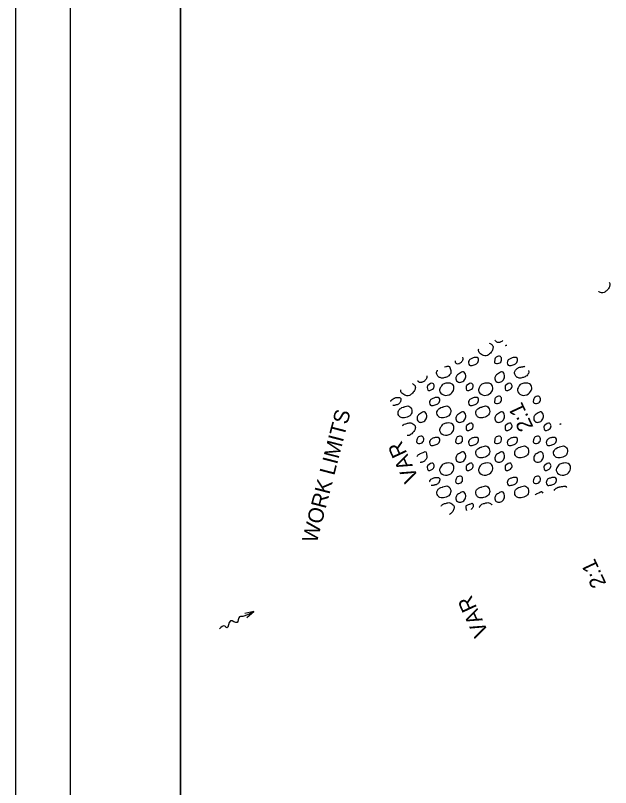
# Model space of a CAD drawing. Extents: x 0 to 2278, y -264 to 330.
# Drawn here: x 0 to 81.2, y 163.9 to 269.1 of the extents above; entities that cross this region are included whole.
import ezdxf

# ---------------------------------------------------------------- set-up
doc = ezdxf.new("R2010")
doc.units = 0
for name, color, linetype in [('DR_P_Culvert', 7, 'Continuous'), ('RW_X_CL_100_Stations', 7, 'Continuous'), ('SC_Scratch1', 7, 'Continuous'), ('XS_P_Finished_Grade', 7, 'Continuous'), ('XS_P_Pavt_Surface', 7, 'Continuous')]:
    doc.layers.add(name, color=color, linetype=linetype)

msp = doc.modelspace()

# ---------------------------------------------------------------- linework, layer by layer
at = {"layer": 'RW_X_CL_100_Stations'}
for points in [[(7.5, 322.5), (22.5, 322.5), (22.5, 7.5), (7.5, 7.5)], [(22.5, 322.5), (502.5, 322.5), (502.5, 7.5), (22.5, 7.5)]]:
    msp.add_lwpolyline(points, close=True, dxfattribs=at)
at = {"layer": 'SC_Scratch1'}
msp.add_lwpolyline([(0, 0), (510, 0), (510, 330), (0, 330)], close=True, dxfattribs=at)
at = {"layer": 'XS_P_Finished_Grade'}
for points, degree in [([(80.96, 232.75), (81.08, 232.59), (81.08, 232.39), (81.03, 232.24), (80.96, 232), (80.82, 231.78), (80.59, 231.58), (80.3, 231.34), (79.91, 231.25), (79.62, 231.42), (79.59, 231.44), (79.56, 231.45), (79.53, 231.47)], 3), ([(64.61, 224.44), (64.72, 224.4), (64.83, 224.34), (64.93, 224.25), (65.13, 224.08), (65.15, 223.83), (65.09, 223.65), (65.03, 223.41), (64.88, 223.19), (64.65, 222.99), (64.37, 222.75), (63.97, 222.65), (63.68, 222.83), (63.44, 222.97), (63.19, 223.18), (63.15, 223.42), (63.13, 223.51), (63.15, 223.6), (63.18, 223.68)], 3), ([(66.48, 224.81), (66.34, 224.67), (66.19, 224.6), (66.03, 224.55), (65.89, 224.51), (65.71, 224.5), (65.57, 224.64), (65.5, 224.71), (65.45, 224.78), (65.41, 224.86)], 3), ([(66.82, 224.12), (66.88, 224.14), (66.94, 224.17), (67, 224.19)], 2), ([(60.96, 222.52), (61.01, 222.41), (61.01, 222.23), (60.98, 222.14), (60.92, 221.98), (60.77, 221.81), (60.62, 221.7), (60.46, 221.58), (60.13, 221.6), (60.04, 221.78), (60, 221.86), (60, 221.94), (60.01, 222.02)], 3), ([(58.49, 221.23), (58.65, 221.25), (58.81, 221.28), (58.96, 221.3), (59.19, 221.33), (59.3, 220.95), (59.35, 220.73), (59.4, 220.54), (59.37, 220.3), (59.21, 220.12), (59.01, 219.9), (58.79, 219.82), (58.54, 219.74), (58.33, 219.68), (58.09, 219.66), (57.88, 219.75), (57.75, 219.8), (57.66, 219.9), (57.58, 220.02), (57.45, 220.22), (57.41, 220.49), (57.53, 220.68), (57.54, 220.7), (57.55, 220.72), (57.56, 220.74)], 3), ([(69.97, 220.7), (70.01, 220.51), (69.97, 220.29), (69.82, 220.12), (69.62, 219.9), (69.39, 219.82), (69.15, 219.74), (68.93, 219.68), (68.7, 219.66), (68.49, 219.75), (68.36, 219.8), (68.27, 219.9), (68.19, 220.02), (68.06, 220.22), (68.02, 220.49), (68.13, 220.68), (68.21, 220.81), (68.31, 220.92), (68.44, 221), (68.55, 221.07), (68.66, 221.14), (68.78, 221.17), (68.82, 221.17), (68.86, 221.18), (68.9, 221.19)], 3), ([(68.89, 221.19), (69.08, 221.22), (69.28, 221.26), (69.47, 221.29)], 2), ([(56.1, 219.97), (56.12, 219.79), (56.07, 219.6), (55.92, 219.43), (55.77, 219.25), (55.6, 219.16), (55.42, 219.11), (55.28, 219.06), (55.1, 219.06), (54.96, 219.2), (54.92, 219.24), (54.88, 219.28), (54.86, 219.32)], 3), ([(54.13, 218.94), (54.19, 218.9), (54.26, 218.86), (54.33, 218.8), (54.53, 218.64), (54.54, 218.39), (54.49, 218.2), (54.42, 217.97), (54.27, 217.74), (54.04, 217.55), (53.76, 217.3), (53.36, 217.21), (53.07, 217.38), (52.83, 217.52), (52.58, 217.73), (52.54, 217.98), (52.53, 218.02), (52.53, 218.06), (52.54, 218.1)], 3), ([(51.18, 216.49), (51.19, 216.54), (51.21, 216.59), (51.24, 216.63), (51.27, 216.68), (51.31, 216.73), (51.35, 216.78)], 3), ([(51.35, 216.78), (51.47, 216.84), (51.6, 216.9), (51.72, 216.96), (51.86, 217.03), (52.03, 217.05), (52.18, 217.05), (52.29, 217.05), (52.39, 217.03), (52.49, 216.93), (52.58, 216.84), (52.57, 216.72), (52.54, 216.62), (52.5, 216.47), (52.44, 216.31), (52.29, 216.18), (52.14, 216.06), (51.98, 216.04), (51.82, 216), (51.7, 215.97), (51.57, 215.92), (51.45, 215.93)], 3), ([(53.01, 213.42), (53.19, 213.46), (53.37, 213.51), (53.54, 213.56), (53.8, 213.62), (54.07, 213.58), (54.33, 213.36), (54.53, 213.19), (54.54, 212.94), (54.49, 212.75), (54.42, 212.52), (54.27, 212.3), (54.04, 212.1), (53.86, 211.95), (53.63, 211.85), (53.42, 211.85)], 3), ([(52.78, 213.17), (52.81, 213.22), (52.85, 213.26), (52.89, 213.3), (52.93, 213.34), (52.97, 213.38), (53.01, 213.42)], 3), ([(74.23, 213.42), (74.28, 213.43), (74.34, 213.45), (74.4, 213.46)], 2), ([(54.8, 208.99), (54.83, 209.09), (54.89, 209.19), (54.98, 209.25), (55.07, 209.31), (55.16, 209.36), (55.25, 209.42)], 3), ([(55.25, 209.42), (55.43, 209.5), (55.6, 209.57), (55.78, 209.65), (55.96, 209.73), (56.05, 209.33), (56.09, 209.14), (56.13, 208.95), (56.08, 208.73), (55.92, 208.54), (55.77, 208.36), (55.6, 208.27), (55.42, 208.22), (55.35, 208.19), (55.27, 208.18), (55.18, 208.19)], 3), ([(56.47, 205.53), (56.48, 205.6), (56.5, 205.68), (56.54, 205.74), (56.58, 205.79), (56.62, 205.84), (56.65, 205.89)], 3), ([(56.65, 205.89), (56.78, 205.95), (56.9, 206.01), (57.03, 206.07), (57.17, 206.14), (57.33, 206.16), (57.48, 206.16), (57.59, 206.16), (57.7, 206.14), (57.8, 206.04), (57.89, 205.95), (57.87, 205.83), (57.85, 205.73), (57.8, 205.58), (57.74, 205.42), (57.59, 205.29), (57.44, 205.16), (57.28, 205.15), (57.12, 205.11), (56.99, 205.08), (56.84, 205.01), (56.7, 205.05)], 3), ([(71.16, 203.98), (71.34, 204.05), (71.52, 204.13), (71.69, 204.2), (71.79, 204.25), (71.86, 204.15), (71.91, 204.02)], 3), ([(73.46, 204.38), (73.53, 204.49), (73.63, 204.59), (73.74, 204.67), (73.85, 204.74), (73.96, 204.8), (74.08, 204.83), (74.12, 204.84), (74.17, 204.85), (74.21, 204.85)], 3), ([(74.19, 204.85), (74.42, 204.89), (74.65, 204.93), (74.88, 204.97), (74.99, 204.98), (75.07, 204.89), (75.14, 204.77)], 3), ([(70.87, 203.78), (70.87, 203.79), (70.88, 203.79), (70.89, 203.8), (70.98, 203.86), (71.07, 203.92), (71.16, 203.98)], 3), ([(58.06, 202.24), (58.1, 202.3), (58.14, 202.36), (58.19, 202.41), (58.23, 202.45), (58.27, 202.49), (58.31, 202.52)], 3), ([(58.31, 202.52), (58.49, 202.57), (58.67, 202.62), (58.85, 202.66), (59.11, 202.73), (59.37, 202.68), (59.63, 202.47), (59.83, 202.3), (59.84, 202.05), (59.79, 201.86), (59.72, 201.63), (59.57, 201.41), (59.35, 201.21), (59.3, 201.17), (59.24, 201.13), (59.19, 201.1)], 3), ([(61.57, 201.65), (61.55, 201.66), (61.53, 201.69), (61.52, 201.72), (61.48, 201.83), (61.47, 201.96), (61.46, 202.08), (61.46, 202.14), (61.44, 202.2), (61.47, 202.26), (61.49, 202.29), (61.5, 202.31), (61.52, 202.34)], 3), ([(61.52, 202.34), (61.76, 202.43), (61.99, 202.53), (62.23, 202.62), (62.35, 202.67), (62.41, 202.41), (62.42, 202.3), (62.43, 202.15), (62.32, 201.99), (62.2, 201.84), (62.18, 201.82), (62.15, 201.8), (62.13, 201.77)], 3), ([(63.24, 202.03), (63.25, 202.06), (63.27, 202.09), (63.29, 202.12), (63.35, 202.22), (63.41, 202.33), (63.5, 202.41), (63.54, 202.45), (63.58, 202.49), (63.62, 202.52)], 3), ([(63.62, 202.52), (63.8, 202.57), (63.97, 202.62), (64.15, 202.66), (64.41, 202.73), (64.67, 202.68), (64.93, 202.47), (64.95, 202.45), (64.96, 202.44), (64.97, 202.43)], 3)]:
    msp.add_open_spline(points, degree=degree, dxfattribs=at)
for points in [[(61.96, 222.22), (62.33, 222.41), (62.78, 222.5), (63.1, 222.38), (63.15, 222.07), (62.89, 221.63), (62.42, 221.45), (61.9, 221.45), (61.77, 221.78), (61.85, 222.08), (61.96, 222.22)], [(65.55, 222.55), (66.13, 222.63), (66.28, 222.14), (65.92, 221.7), (65.34, 221.78), (65.35, 222.15), (65.43, 222.4), (65.55, 222.55)], [(67.26, 222.22), (67.64, 222.41), (68.09, 222.5), (68.4, 222.38), (68.45, 222.07), (68.2, 221.63), (67.73, 221.45), (67.2, 221.45), (67.07, 221.78), (67.15, 222.08), (67.26, 222.22)], [(60.56, 220.32), (61.08, 220.54), (61.4, 220.03), (61.23, 219.43), (60.73, 219.11), (60.26, 219.2), (60.06, 219.74), (60.28, 220.14), (60.56, 220.32)], [(65.86, 220.32), (66.39, 220.54), (66.7, 220.03), (66.53, 219.43), (66.03, 219.11), (65.57, 219.2), (65.37, 219.74), (65.58, 220.14), (65.86, 220.32)], [(56.22, 218.67), (56.93, 218.96), (57.12, 218.63), (56.89, 218.18), (56.22, 218.05), (56.16, 218.41), (56.17, 218.6), (56.22, 218.67)], [(58.31, 218.86), (58.85, 219), (59.63, 218.8), (59.79, 218.2), (59.35, 217.55), (58.37, 217.38), (57.84, 217.98), (57.99, 218.46), (58.19, 218.75), (58.31, 218.86)], [(61.52, 218.67), (62.23, 218.96), (62.42, 218.63), (62.2, 218.18), (61.52, 218.05), (61.46, 218.41), (61.47, 218.6), (61.52, 218.67)], [(63.62, 218.86), (64.15, 219), (64.93, 218.8), (65.09, 218.2), (64.65, 217.55), (63.68, 217.38), (63.15, 217.98), (63.29, 218.46), (63.5, 218.75), (63.62, 218.86)], [(66.82, 218.67), (67.54, 218.96), (67.72, 218.63), (67.5, 218.18), (66.83, 218.05), (66.77, 218.41), (66.77, 218.6), (66.82, 218.67)], [(68.92, 218.86), (69.46, 219), (70.24, 218.8), (70.4, 218.2), (69.95, 217.55), (68.98, 217.38), (68.45, 217.98), (68.59, 218.46), (68.8, 218.75), (68.92, 218.86)], [(56.65, 216.78), (57.03, 216.96), (57.48, 217.05), (57.8, 216.93), (57.85, 216.62), (57.59, 216.18), (57.12, 216), (56.59, 216.01), (56.46, 216.33), (56.54, 216.63), (56.65, 216.78)], [(61.96, 216.78), (62.33, 216.96), (62.78, 217.05), (63.1, 216.93), (63.15, 216.62), (62.89, 216.18), (62.42, 216), (61.9, 216.01), (61.77, 216.33), (61.85, 216.63), (61.96, 216.78)], [(65.55, 217.1), (66.13, 217.19), (66.28, 216.69), (65.92, 216.25), (65.34, 216.34), (65.35, 216.71), (65.43, 216.95), (65.55, 217.1)], [(70.86, 217.1), (71.43, 217.19), (71.59, 216.69), (71.23, 216.25), (70.65, 216.34), (70.65, 216.71), (70.74, 216.95), (70.86, 217.1)], [(52.98, 215.74), (53.66, 215.86), (54.05, 215.29), (53.9, 214.68), (53.24, 214.3), (52.58, 214.3), (52.28, 214.57), (52.22, 215.24), (52.53, 215.56), (52.87, 215.72), (52.99, 215.75)], [(58.28, 215.74), (58.96, 215.86), (59.35, 215.29), (59.21, 214.68), (58.54, 214.3), (57.88, 214.3), (57.58, 214.57), (57.53, 215.24), (57.83, 215.56), (58.17, 215.72), (58.3, 215.75)], [(63.59, 215.74), (64.27, 215.86), (64.66, 215.29), (64.51, 214.68), (63.84, 214.3), (63.18, 214.3), (62.88, 214.57), (62.83, 215.24), (63.14, 215.56), (63.48, 215.72), (63.6, 215.75)], [(55.25, 214.87), (55.78, 215.1), (56.09, 214.59), (55.92, 213.98), (55.42, 213.66), (54.96, 213.75), (54.76, 214.29), (54.98, 214.69), (55.25, 214.87)], [(60.56, 214.87), (61.08, 215.1), (61.4, 214.59), (61.23, 213.98), (60.73, 213.66), (60.26, 213.75), (60.06, 214.29), (60.28, 214.69), (60.56, 214.87)], [(65.86, 214.87), (66.39, 215.1), (66.7, 214.59), (66.53, 213.98), (66.03, 213.66), (65.57, 213.75), (65.37, 214.29), (65.58, 214.69), (65.86, 214.87)], [(71.16, 214.87), (71.69, 215.1), (72, 214.59), (71.84, 213.98), (71.34, 213.66), (70.87, 213.75), (70.67, 214.29), (70.89, 214.69), (71.16, 214.87)], [(58.31, 213.42), (58.85, 213.56), (59.63, 213.36), (59.79, 212.75), (59.35, 212.1), (58.37, 211.94), (57.84, 212.53), (57.99, 213.01), (58.19, 213.3), (58.31, 213.42)], [(61.52, 213.23), (62.23, 213.52), (62.42, 213.19), (62.2, 212.73), (61.52, 212.61), (61.46, 212.97), (61.47, 213.15), (61.52, 213.23)], [(66.82, 213.23), (67.54, 213.52), (67.72, 213.19), (67.5, 212.73), (66.83, 212.61), (66.77, 212.97), (66.77, 213.15), (66.82, 213.23)], [(72.13, 213.23), (72.84, 213.52), (73.03, 213.19), (72.8, 212.73), (72.13, 212.61), (72.07, 212.97), (72.08, 213.15), (72.13, 213.23)], [(54.95, 211.66), (55.52, 211.74), (55.68, 211.25), (55.32, 210.81), (54.74, 210.89), (54.74, 211.26), (54.83, 211.51), (54.95, 211.66)], [(56.65, 211.33), (57.03, 211.52), (57.48, 211.61), (57.8, 211.48), (57.85, 211.18), (57.59, 210.73), (57.12, 210.55), (56.59, 210.56), (56.46, 210.89), (56.54, 211.19), (56.65, 211.33)], [(60.25, 211.66), (60.82, 211.74), (60.98, 211.25), (60.62, 210.81), (60.04, 210.89), (60.04, 211.26), (60.13, 211.51), (60.25, 211.66)], [(61.96, 211.33), (62.33, 211.52), (62.78, 211.61), (63.1, 211.48), (63.15, 211.18), (62.89, 210.73), (62.42, 210.55), (61.9, 210.56), (61.77, 210.89), (61.85, 211.19), (61.96, 211.33)], [(65.55, 211.66), (66.13, 211.74), (66.28, 211.25), (65.92, 210.81), (65.34, 210.89), (65.35, 211.26), (65.43, 211.51), (65.55, 211.66)], [(67.26, 211.33), (67.64, 211.52), (68.09, 211.61), (68.4, 211.48), (68.45, 211.18), (68.2, 210.73), (67.73, 210.55), (67.2, 210.56), (67.07, 210.89), (67.15, 211.19), (67.26, 211.33)], [(70.86, 211.66), (71.43, 211.74), (71.59, 211.25), (71.23, 210.81), (70.65, 210.89), (70.65, 211.26), (70.74, 211.51), (70.86, 211.66)], [(72.56, 211.33), (72.94, 211.52), (73.39, 211.61), (73.71, 211.48), (73.76, 211.18), (73.5, 210.73), (73.03, 210.55), (72.5, 210.56), (72.38, 210.89), (72.45, 211.19), (72.56, 211.33)], [(63.59, 210.3), (64.27, 210.41), (64.66, 209.84), (64.51, 209.23), (63.84, 208.85), (63.18, 208.86), (62.88, 209.12), (62.83, 209.79), (63.14, 210.11), (63.48, 210.27), (63.6, 210.3)], [(68.89, 210.3), (69.57, 210.41), (69.96, 209.84), (69.82, 209.23), (69.15, 208.85), (68.49, 208.86), (68.19, 209.12), (68.13, 209.79), (68.44, 210.11), (68.78, 210.27), (68.9, 210.3)], [(74.19, 210.3), (74.88, 210.41), (75.26, 209.84), (75.12, 209.23), (74.45, 208.85), (73.79, 208.86), (73.49, 209.12), (73.44, 209.79), (73.74, 210.11), (74.08, 210.27), (74.21, 210.3)], [(60.56, 209.42), (61.08, 209.65), (61.4, 209.14), (61.23, 208.54), (60.73, 208.22), (60.26, 208.31), (60.06, 208.84), (60.28, 209.25), (60.56, 209.42)], [(65.86, 209.42), (66.39, 209.65), (66.7, 209.14), (66.53, 208.54), (66.03, 208.22), (65.57, 208.31), (65.37, 208.84), (65.58, 209.25), (65.86, 209.42)], [(71.16, 209.42), (71.69, 209.65), (72, 209.14), (71.84, 208.54), (71.34, 208.22), (70.87, 208.31), (70.67, 208.84), (70.89, 209.25), (71.16, 209.42)], [(56.22, 207.78), (56.93, 208.07), (57.12, 207.74), (56.89, 207.29), (56.22, 207.16), (56.16, 207.52), (56.17, 207.7), (56.22, 207.78)], [(58.31, 207.97), (58.85, 208.11), (59.63, 207.91), (59.79, 207.31), (59.35, 206.66), (58.37, 206.49), (57.84, 207.09), (57.99, 207.57), (58.19, 207.85), (58.31, 207.97)], [(61.52, 207.78), (62.23, 208.07), (62.42, 207.74), (62.2, 207.29), (61.52, 207.16), (61.46, 207.52), (61.47, 207.7), (61.52, 207.78)], [(63.62, 207.97), (64.15, 208.11), (64.93, 207.91), (65.09, 207.31), (64.65, 206.66), (63.68, 206.49), (63.15, 207.09), (63.29, 207.57), (63.5, 207.85), (63.62, 207.97)], [(66.82, 207.78), (67.54, 208.07), (67.72, 207.74), (67.5, 207.29), (66.83, 207.16), (66.77, 207.52), (66.77, 207.7), (66.82, 207.78)], [(72.13, 207.78), (72.84, 208.07), (73.03, 207.74), (72.8, 207.29), (72.13, 207.16), (72.07, 207.52), (72.08, 207.7), (72.13, 207.78)], [(74.23, 207.97), (74.76, 208.11), (75.54, 207.91), (75.7, 207.31), (75.26, 206.66), (74.29, 206.49), (73.75, 207.09), (73.9, 207.57), (74.1, 207.85), (74.23, 207.97)], [(60.25, 206.21), (60.82, 206.29), (60.98, 205.8), (60.62, 205.36), (60.04, 205.45), (60.04, 205.81), (60.13, 206.06), (60.25, 206.21)], [(70.86, 206.21), (71.43, 206.29), (71.59, 205.8), (71.23, 205.36), (70.65, 205.45), (70.65, 205.81), (70.74, 206.06), (70.86, 206.21)], [(67.26, 205.89), (67.64, 206.07), (68.09, 206.16), (68.4, 206.04), (68.45, 205.73), (68.2, 205.29), (67.73, 205.11), (67.2, 205.12), (67.07, 205.44), (67.15, 205.74), (67.26, 205.89)], [(72.56, 205.89), (72.94, 206.07), (73.39, 206.16), (73.71, 206.04), (73.76, 205.73), (73.5, 205.29), (73.03, 205.11), (72.5, 205.12), (72.38, 205.44), (72.45, 205.74), (72.56, 205.89)], [(58.28, 204.85), (58.96, 204.97), (59.35, 204.4), (59.21, 203.79), (58.54, 203.41), (57.88, 203.41), (57.58, 203.68), (57.53, 204.35), (57.83, 204.67), (58.17, 204.83), (58.3, 204.85)], [(60.56, 203.98), (61.08, 204.2), (61.4, 203.7), (61.23, 203.09), (60.73, 202.77), (60.26, 202.86), (60.06, 203.4), (60.28, 203.8), (60.56, 203.98)], [(63.59, 204.85), (64.27, 204.97), (64.66, 204.4), (64.51, 203.79), (63.84, 203.41), (63.18, 203.41), (62.88, 203.68), (62.83, 204.35), (63.14, 204.67), (63.48, 204.83), (63.6, 204.85)], [(65.86, 203.98), (66.39, 204.2), (66.7, 203.7), (66.53, 203.09), (66.03, 202.77), (65.57, 202.86), (65.37, 203.4), (65.58, 203.8), (65.86, 203.98)], [(68.89, 204.85), (69.57, 204.97), (69.96, 204.4), (69.82, 203.79), (69.15, 203.41), (68.49, 203.41), (68.19, 203.68), (68.13, 204.35), (68.44, 204.67), (68.78, 204.83), (68.9, 204.85)]]:
    msp.add_spline(points, degree=3, dxfattribs=at)
at = {"layer": 'XS_P_Pavt_Surface'}
for p, q in [((32.49, 187.89), (31.27, 187.63)), ((31.57, 187.06), (32.49, 187.89))]:
    msp.add_line(p, q, dxfattribs=at)
msp.add_spline([(32.49, 187.89), (31.38, 187.32), (30.89, 187.2), (30.56, 187.16), (30.24, 186.38), (29.31, 186.6), (28.84, 185.67), (28.54, 185.89), (27.81, 185.51)], degree=3, dxfattribs=at)

# ---------------------------------------------------------------- texts
at = {"layer": 'DR_P_Culvert'}
for s, rotation, p in [('2:1', 114.9993, (70.67, 213.01)), ('WORK LIMITS', 75.5015, (41.08, 197.11)), ('VAR', 114.7698, (55.01, 206.03)), ('2:1', 114.9993, (80.61, 191.68)), ('VAR', 114.7698, (64.54, 184.99))]:
    msp.add_text(s, height=2.1, rotation=rotation, dxfattribs=at).set_placement(p)

doc.saveas('drawing.dxf')
